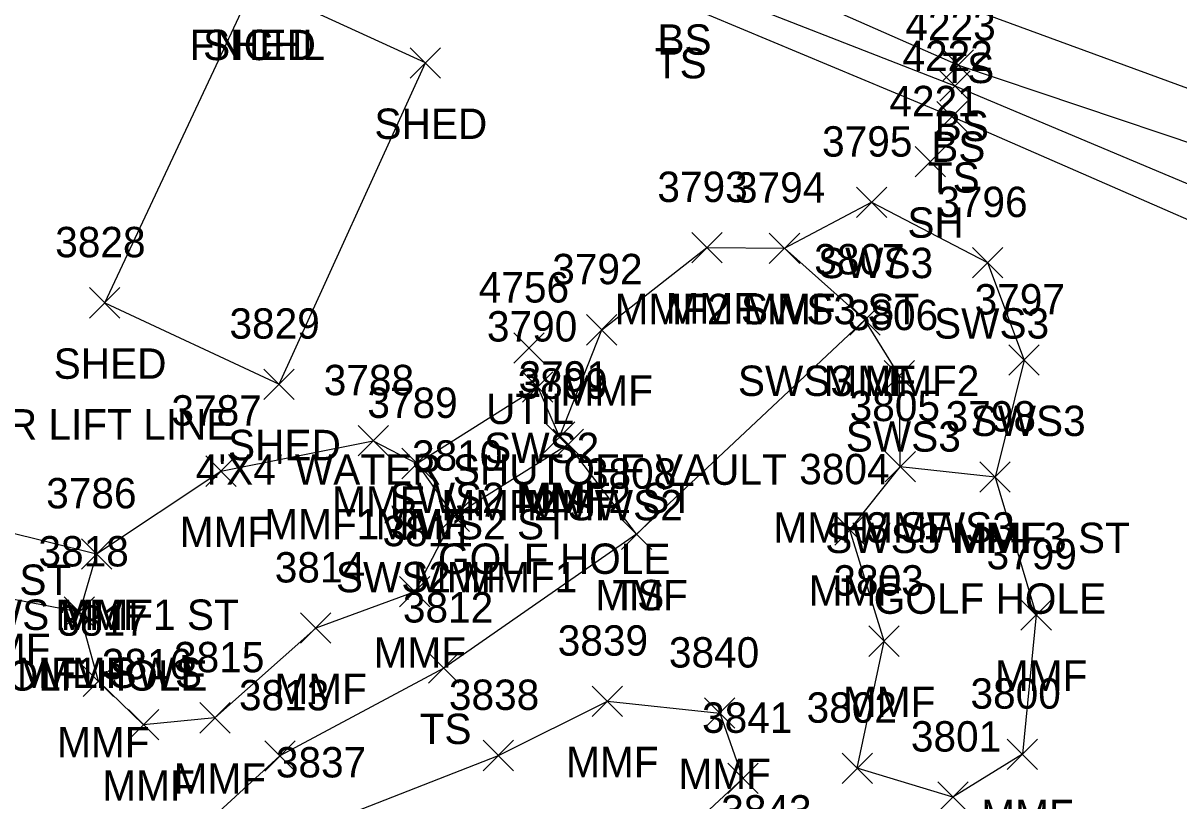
# Model space of a CAD drawing. Extents: x 49137 to 50946, y 9590 to 10709.
# Drawn here: x 50054.1 to 50130.2, y 10375 to 10426.2 of the extents above; entities that cross this region are included whole.
import ezdxf

# ---------------------------------------------------------------- set-up
doc = ezdxf.new("R2010")
doc.units = 0
for name, color, linetype in [('L_A', 7, 'Continuous'), ('L_C', 7, 'Continuous'), ('L_I', 7, 'Continuous'), ('L_TIC', 7, 'Continuous'), ('LBC', 7, 'Continuous'), ('LDEFAULT', 7, 'Continuous'), ('LELB', 7, 'Continuous'), ('R_A', 7, 'Continuous'), ('R_C', 7, 'Continuous'), ('R_I', 7, 'Continuous'), ('R_TIC', 7, 'Continuous'), ('RSW', 7, 'Continuous'), ('U_A', 7, 'Continuous'), ('U_C', 7, 'Continuous'), ('U_I', 7, 'Continuous'), ('UDEFAULT', 7, 'Continuous')]:
    doc.layers.add(name, color=color, linetype=linetype)

msp = doc.modelspace()

# ---------------------------------------------------------------- linework, layer by layer
at = {"layer": 'L_TIC'}
for points in [[(50079.615, 10422.582), (50081.615, 10424.582)], [(50081.615, 10422.582), (50079.615, 10424.582)], [(50114.708, 10422.44), (50116.708, 10424.44)], [(50116.708, 10422.44), (50114.708, 10424.44)], [(50114.479, 10421.07), (50116.479, 10423.07)], [(50116.479, 10421.07), (50114.479, 10423.07)], [(50114.286, 10419.049), (50116.286, 10421.049)], [(50116.286, 10419.049), (50114.286, 10421.049)], [(50112.86, 10416.078), (50114.86, 10418.078)], [(50114.86, 10416.078), (50112.86, 10418.078)], [(50098.146, 10410.431), (50100.146, 10412.431)], [(50100.146, 10410.431), (50098.146, 10412.431)], [(50103.257, 10410.385), (50105.257, 10412.385)], [(50105.257, 10410.385), (50103.257, 10412.385)], [(50058.492, 10406.792), (50060.492, 10408.792)], [(50060.492, 10406.792), (50058.492, 10408.792)], [(50058.492, 10406.792), (50060.492, 10408.792)], [(50060.492, 10406.792), (50058.492, 10408.792)], [(50108.552, 10405.662), (50110.552, 10407.662)], [(50110.552, 10405.662), (50108.552, 10407.662)], [(50091.222, 10405.016), (50093.222, 10407.016)], [(50093.222, 10405.016), (50091.222, 10407.016)], [(50069.974, 10401.432), (50071.974, 10403.432)], [(50071.974, 10401.432), (50069.974, 10403.432)], [(50088.44, 10397.947), (50090.44, 10399.947)], [(50090.44, 10397.947), (50088.44, 10399.947)], [(50076.177, 10397.71), (50078.177, 10399.71)], [(50078.177, 10397.71), (50076.177, 10399.71)], [(50089.022, 10397.475), (50091.022, 10399.475)], [(50091.022, 10397.475), (50089.022, 10399.475)], [(50066.145, 10395.71), (50068.145, 10397.71)], [(50068.145, 10395.71), (50066.145, 10397.71)], [(50079.054, 10396.215), (50081.054, 10398.215)], [(50081.054, 10396.215), (50079.054, 10398.215)], [(50110.885, 10396.005), (50112.885, 10398.005)], [(50112.885, 10396.005), (50110.885, 10398.005)], [(50117.129, 10395.319), (50119.129, 10397.319)], [(50119.129, 10395.319), (50117.129, 10397.319)], [(50081.51, 10392.739), (50083.51, 10394.739)], [(50083.51, 10392.739), (50081.51, 10394.739)], [(50107.566, 10391.849), (50109.566, 10393.849)], [(50109.566, 10391.849), (50107.566, 10393.849)], [(50093.516, 10391.553), (50095.516, 10393.553)], [(50095.516, 10391.553), (50093.516, 10393.553)], [(50093.516, 10391.553), (50095.516, 10393.553)], [(50095.516, 10391.553), (50093.516, 10393.553)], [(50057.954, 10390.261), (50059.954, 10392.261)], [(50059.954, 10390.261), (50057.954, 10392.261)], [(50078.912, 10387.771), (50080.912, 10389.771)], [(50080.912, 10387.771), (50078.912, 10389.771)], [(50056.822, 10386.436), (50058.822, 10388.436)], [(50058.822, 10386.436), (50056.822, 10388.436)], [(50119.83, 10386.248), (50121.83, 10388.248)], [(50121.83, 10386.248), (50119.83, 10388.248)], [(50072.384, 10385.381), (50074.384, 10387.381)], [(50074.384, 10385.381), (50072.384, 10387.381)], [(50109.818, 10384.519), (50111.818, 10386.519)], [(50111.818, 10384.519), (50109.818, 10386.519)], [(50080.82, 10382.745), (50082.82, 10384.745)], [(50082.82, 10382.745), (50080.82, 10384.745)], [(50058.074, 10381.878), (50060.074, 10383.878)], [(50060.074, 10381.878), (50058.074, 10383.878)], [(50091.593, 10380.563), (50093.593, 10382.563)], [(50093.593, 10380.563), (50091.593, 10382.563)], [(50098.991, 10379.781), (50100.991, 10381.781)], [(50100.991, 10379.781), (50098.991, 10381.781)], [(50061.051, 10379.013), (50063.051, 10381.013)], [(50063.051, 10379.013), (50061.051, 10381.013)], [(50065.749, 10379.47), (50067.749, 10381.47)], [(50067.749, 10379.47), (50065.749, 10381.47)], [(50070.028, 10376.965), (50072.028, 10378.965)], [(50072.028, 10376.965), (50070.028, 10378.965)], [(50070.028, 10376.965), (50072.028, 10378.965)], [(50072.028, 10376.965), (50070.028, 10378.965)], [(50084.418, 10376.99), (50086.418, 10378.99)], [(50086.418, 10376.99), (50084.418, 10378.99)], [(50118.929, 10377.073), (50120.929, 10379.073)], [(50120.929, 10377.073), (50118.929, 10379.073)], [(50108.054, 10376.148), (50110.054, 10378.148)], [(50110.054, 10376.148), (50108.054, 10378.148)], [(50100.522, 10375.482), (50102.522, 10377.482)], [(50102.522, 10375.482), (50100.522, 10377.482)], [(50114.351, 10374.251), (50116.351, 10376.251)], [(50116.351, 10374.251), (50114.351, 10376.251)]]:
    msp.add_lwpolyline(points, dxfattribs=at)
at = {"layer": 'LBC'}
for points in [[(50059.492, 10407.792), (50070.974, 10402.432), (50080.615, 10423.582), (50069.33, 10428.771)], [(50059.492, 10407.792), (50069.33, 10428.771)]]:
    msp.add_lwpolyline(points, dxfattribs=at)
at = {"layer": 'LDEFAULT'}
for points in [[(50089.44, 10398.947), (50092.222, 10406.016), (50099.146, 10411.431), (50104.257, 10411.385), (50109.552, 10406.662), (50094.516, 10392.553), (50090.022, 10398.475)], [(50058.954, 10391.261), (50067.145, 10396.71), (50077.177, 10398.71), (50080.054, 10397.215), (50082.51, 10393.739), (50079.912, 10388.771), (50073.384, 10386.381), (50066.749, 10380.47), (50062.051, 10380.013), (50059.074, 10382.878), (50057.822, 10387.436)], [(50118.129, 10396.319), (50120.83, 10387.248), (50119.929, 10378.073), (50115.351, 10375.251), (50109.054, 10377.148), (50110.818, 10385.519), (50108.566, 10392.849), (50111.885, 10397.005)], [(50068.582, 10366.974), (50071.497, 10368.385), (50074.021, 10373.547), (50085.418, 10377.99), (50092.593, 10381.563), (50099.991, 10380.781), (50101.522, 10376.482), (50094.319, 10369.779), (50086.385, 10366.087), (50076.367, 10360.97), (50079.378, 10354.287), (50086.909, 10359.213), (50092.608, 10363.171), (50099.002, 10362.503), (50106.202, 10359.709), (50108.802, 10358.745), (50107.709, 10354.68), (50105.964, 10353.299), (50102.437, 10354.887), (50092.501, 10352.083), (50082.783, 10347.369), (50078.379, 10346.819)]]:
    msp.add_lwpolyline(points, dxfattribs=at)
at = {"layer": 'LELB'}
for points in [[(49990.199, 10501.293), (49995.79, 10490.374), (50015.157, 10492.779), (50039.005, 10474.292), (50057.869, 10465.322), (50068.063, 10442.777), (50097.447, 10429.125), (50115.479, 10422.07), (50146.004, 10409.248), (50171.194, 10398.053), (50180.097, 10394.504), (50181.066, 10396.537)], [(50061.492, 10473.052), (50073.503, 10455.324), (50099.28, 10434.681), (50116.24, 10427.258), (50148.873, 10415.298), (50177.239, 10402.221), (50187.409, 10396.186)], [(50057.869, 10465.322), (50070.634, 10448.936), (50097.796, 10431.335), (50115.708, 10423.44), (50147.59, 10412.74), (50170.334, 10401.028), (50181.066, 10396.537)], [(50068.063, 10442.777), (50097.309, 10427.571), (50115.286, 10420.049), (50145.232, 10406.974), (50168.914, 10397.098), (50186.368, 10390.433)], [(50094.516, 10392.553), (50081.82, 10383.745), (50071.028, 10377.965)], [(50019.697, 10350.956), (50018.697, 10360.413), (50027.458, 10369.871), (50043.148, 10372.476), (50051.46, 10367.333), (50060.907, 10368.69), (50071.028, 10377.965)]]:
    msp.add_lwpolyline(points, dxfattribs=at)
at = {"layer": 'R_TIC'}
for points in [[(50108.993, 10413.417), (50110.993, 10415.417)], [(50110.993, 10413.417), (50108.993, 10415.417)], [(50103.257, 10410.385), (50105.257, 10412.385)], [(50105.257, 10410.385), (50103.257, 10412.385)], [(50116.633, 10409.438), (50118.633, 10411.438)], [(50118.633, 10409.438), (50116.633, 10411.438)], [(50108.552, 10405.662), (50110.552, 10407.662)], [(50110.552, 10405.662), (50108.552, 10407.662)], [(50119.039, 10403.025), (50121.039, 10405.025)], [(50121.039, 10403.025), (50119.039, 10405.025)], [(50110.82, 10401.995), (50112.82, 10403.995)], [(50112.82, 10401.995), (50110.82, 10403.995)], [(50087.008, 10401.244), (50089.008, 10403.244)], [(50089.008, 10401.244), (50087.008, 10403.244)], [(50088.44, 10397.947), (50090.44, 10399.947)], [(50090.44, 10397.947), (50088.44, 10399.947)], [(50089.022, 10397.475), (50091.022, 10399.475)], [(50091.022, 10397.475), (50089.022, 10399.475)], [(50079.054, 10396.215), (50081.054, 10398.215)], [(50081.054, 10396.215), (50079.054, 10398.215)], [(50110.885, 10396.005), (50112.885, 10398.005)], [(50112.885, 10396.005), (50110.885, 10398.005)], [(50117.129, 10395.319), (50119.129, 10397.319)], [(50119.129, 10395.319), (50117.129, 10397.319)], [(50081.51, 10392.739), (50083.51, 10394.739)], [(50083.51, 10392.739), (50081.51, 10394.739)], [(50057.954, 10390.261), (50059.954, 10392.261)], [(50059.954, 10390.261), (50057.954, 10392.261)], [(50056.822, 10386.436), (50058.822, 10388.436)], [(50058.822, 10386.436), (50056.822, 10388.436)]]:
    msp.add_lwpolyline(points, dxfattribs=at)
at = {"layer": 'RSW'}
for points in [[(50104.257, 10411.385), (50109.993, 10414.417), (50117.633, 10410.438), (50120.039, 10404.025), (50118.129, 10396.319), (50111.885, 10397.005), (50111.82, 10402.995), (50109.552, 10406.662)], [(50080.054, 10397.215), (50088.008, 10402.244), (50089.44, 10398.947), (50090.022, 10398.475), (50082.51, 10393.739)], [(50049.646, 10393.563), (50058.954, 10391.261), (50057.822, 10387.436), (50049.621, 10389.018)]]:
    msp.add_lwpolyline(points, dxfattribs=at)
at = {"layer": 'UDEFAULT'}
for points in [[(50086.438, 10403.812), (50088.438, 10405.812)], [(50088.438, 10403.812), (50086.438, 10405.812)]]:
    msp.add_lwpolyline(points, dxfattribs=at)

# ---------------------------------------------------------------- texts
at = {"layer": 'L_A'}
for s, p in [('FNCHL', (50065.078, 10423.771)), ('SHED', (50065.968, 10423.771)), ('SHED', (50065.968, 10423.771)), ('BS', (50095.888, 10424.125)), ('TS', (50095.718, 10422.571)), ('TS', (50114.649, 10422.258)), ('SHED', (50077.253, 10418.582)), ('BS', (50114.149, 10418.44)), ('BS', (50113.92, 10417.07)), ('TS', (50113.695, 10415.049)), ('SH', (50112.348, 10412.078)), ('MMF', (50096.429, 10406.431)), ('MMF', (50101.54, 10406.385)), ('SHED', (50056.13, 10402.792)), ('SHED', (50056.13, 10402.792)), ('MMF', (50106.836, 10401.662)), ('MMF', (50089.506, 10401.016)), ('SHED', (50067.612, 10397.432)), ('MMF', (50086.723, 10393.947)), ('MMF', (50074.46, 10393.71)), ('MMF', (50087.306, 10393.475)), ('MMF', (50064.429, 10391.71)), ('MMF', (50077.338, 10392.215)), ('MMF', (50109.169, 10392.005)), ('MMF', (50115.412, 10391.319)), ('MMF', (50079.793, 10388.739)), ('MMF', (50105.85, 10387.849)), ('MMF', (50091.8, 10387.553)), ('TS', (50092.926, 10387.553)), ('MMF', (50056.238, 10386.261)), ('MMF', (50077.195, 10383.771)), ('MMF', (50055.105, 10382.436)), ('MMF', (50118.114, 10382.248)), ('MMF', (50070.668, 10381.381)), ('MMF', (50108.101, 10380.519)), ('TS', (50080.229, 10378.745)), ('MMF', (50056.357, 10377.878)), ('MMF', (50089.876, 10376.563)), ('MMF', (50097.274, 10375.781)), ('MMF', (50059.335, 10375.013)), ('MMF', (50064.032, 10375.47)), ('MMF', (50117.213, 10373.073))]:
    msp.add_text(s, height=2, dxfattribs=at).set_placement(p)
at = {"layer": 'L_C'}
msp.add_text('T-BAR LIFT LINE', height=2, dxfattribs=at).set_placement((50047.02, 10398.792))
msp.add_text('T-BAR LIFT LINE', height=2, dxfattribs=at).set_placement((50047.02, 10398.792))
at = {"layer": 'L_I'}
for s, p in [('4223', (50112.219, 10425.07)), ('4222', (50112.026, 10423.049)), ('4221', (50111.167, 10420.078)), ('3793', (50095.886, 10414.431)), ('3794', (50100.997, 10414.385)), ('3828', (50056.232, 10410.792)), ('3828', (50056.232, 10410.792)), ('3807', (50106.214, 10409.662)), ('3792', (50088.963, 10409.016)), ('3829', (50067.707, 10405.432)), ('3788', (50073.917, 10401.71)), ('3791', (50086.747, 10401.947)), ('3809', (50086.676, 10401.475)), ('3789', (50076.787, 10400.215)), ('3805', (50108.547, 10400.005)), ('3787', (50063.886, 10399.71)), ('3798', (50114.869, 10399.319)), ('3810', (50079.731, 10396.739)), ('3808', (50091.178, 10395.553)), ('3808', (50091.178, 10395.553)), ('3804', (50105.228, 10395.849)), ('3786', (50055.639, 10394.261)), ('3811', (50077.786, 10391.771)), ('3818', (50055.129, 10390.436)), ('3799', (50117.563, 10390.248)), ('3814', (50070.692, 10389.381)), ('3803', (50107.479, 10388.519)), ('3812', (50079.127, 10386.745)), ('3817', (50056.381, 10385.878)), ('3839', (50089.325, 10384.563)), ('3815', (50064.056, 10383.47)), ('3840', (50096.644, 10383.781)), ('3816', (50059.303, 10383.013)), ('3813', (50068.336, 10380.965)), ('3813', (50068.336, 10380.965)), ('3838', (50082.158, 10380.99)), ('3800', (50116.504, 10381.073)), ('3841', (50098.829, 10379.482)), ('3802', (50105.715, 10380.148)), ('3801', (50112.579, 10378.251)), ('3837', (50070.762, 10376.547)), ('3843', (50100.093, 10373.38))]:
    msp.add_text(s, height=2, dxfattribs=at).set_placement(p)
at = {"layer": 'R_A'}
for s, p in [('SWS3', (50106.466, 10409.417)), ('MMF2 SWS3 ST', (50093.068, 10406.385)), ('SWS3', (50114.105, 10405.438)), ('SWS3 MMF2', (50101.19, 10401.662)), ('SWS3', (50116.512, 10399.025)), ('SWS3', (50108.293, 10397.995)), ('SWS2', (50084.48, 10397.244)), ('SWS2 MMF2 ST', (50078.251, 10393.947)), ('MMF2 SWS2', (50081.66, 10393.475)), ('MMF1 SWS2 ST', (50069.999, 10392.215)), ('MMF3 SWS3', (50103.523, 10392.005)), ('SWS3 MMF3 ST', (50106.94, 10391.319)), ('SWS2 MMF1', (50074.715, 10388.739)), ('MMF SWS ST', (50040.205, 10388.563)), ('SWS MMF1 ST', (50049.75, 10386.261)), ('SWS MMF', (50042.999, 10384.018)), ('MMF1 SWS', (50051.491, 10382.436))]:
    msp.add_text(s, height=2, dxfattribs=at).set_placement(p)
at = {"layer": 'R_C'}
for p in [(50081.44, 10389.947), (50110.129, 10387.319), (50050.954, 10382.261)]:
    msp.add_text('GOLF HOLE', height=2, dxfattribs=at).set_placement(p)
at = {"layer": 'R_I'}
for s, p in [('3795', (50106.733, 10417.417)), ('3794', (50100.997, 10414.385)), ('3796', (50114.318, 10413.438)), ('3807', (50106.214, 10409.662)), ('3797', (50116.78, 10407.025)), ('3806', (50108.427, 10405.995)), ('3790', (50084.662, 10405.244)), ('3791', (50086.747, 10401.947)), ('3809', (50086.676, 10401.475)), ('3789', (50076.787, 10400.215)), ('3805', (50108.547, 10400.005)), ('3798', (50114.869, 10399.319)), ('3810', (50079.731, 10396.739)), ('3786', (50055.639, 10394.261)), ('3818', (50055.129, 10390.436))]:
    msp.add_text(s, height=2, dxfattribs=at).set_placement(p)
at = {"layer": 'U_A'}
msp.add_text('UTIL', height=2, dxfattribs=at).set_placement((50084.603, 10399.812))
at = {"layer": 'U_C'}
msp.add_text("4'X4' WATER SHUTOFF VAULT", height=2, dxfattribs=at).set_placement((50065.493, 10395.812))
at = {"layer": 'U_I'}
msp.add_text('4756', height=2, dxfattribs=at).set_placement((50084.123, 10407.812))

doc.saveas('drawing.dxf')
